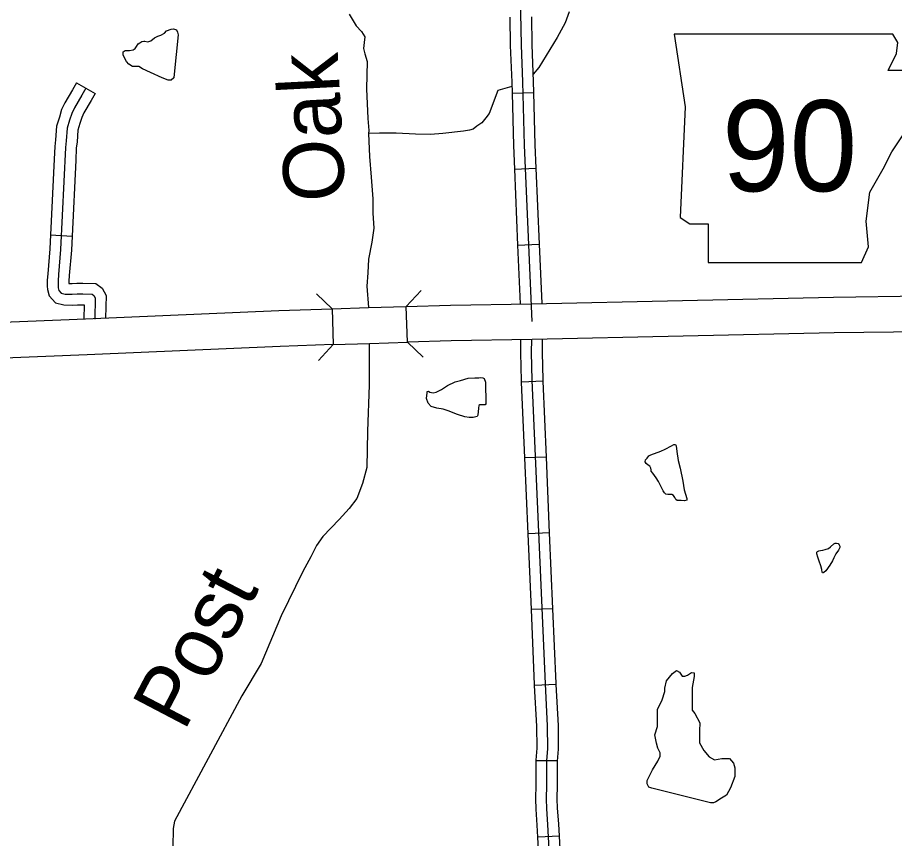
# Model space of a CAD drawing. Extents: x -5566 to 1759129, y -3726 to 731467.
# Drawn here: x -4559.17 to -4512.81, y 255.2 to 298.58 of the extents above; entities that cross this region are included whole.
import ezdxf

# ---------------------------------------------------------------- set-up
doc = ezdxf.new("R2010")
doc.units = 0
doc.layers.add('Default', color=7, linetype='Continuous')

msp = doc.modelspace()

# ---------------------------------------------------------------- linework, layer by layer
at = {"layer": 'Default'}
for p, q in [((-4556.053, 295.124), (-4555.065, 294.557)), ((-4533.027, 294.581), (-4531.889, 294.611)), ((-4532.902, 290.565), (-4531.763, 290.613)), ((-4557.423, 287.089), (-4556.285, 287.035)), ((-4532.731, 286.558), (-4531.593, 286.607)), ((-4531.384, 279.363), (-4532.522, 279.315)), ((-4531.212, 275.357), (-4532.35, 275.309)), ((-4531.04, 271.351), (-4532.178, 271.303)), ((-4530.868, 267.345), (-4532.006, 267.296)), ((-4530.696, 263.346), (-4531.833, 263.284)), ((-4530.619, 259.31), (-4531.758, 259.311)), ((-4530.527, 255.334), (-4531.665, 255.274))]:
    msp.add_line(p, q, dxfattribs=at)
for points in [[(-4533.588, 322.21), (-4533.452, 319.715), (-4533.448, 319.094), (-4533.525, 317.394), (-4533.512, 315.103), (-4533.614, 313.624), (-4533.583, 312.543), (-4533.528, 311.702), (-4533.389, 310.302), (-4533.282, 308.917), (-4533.035, 306.147), (-4532.777, 302.561), (-4532.669, 301.437), (-4532.594, 299.684), (-4532.55, 297.117), (-4532.473, 295.185), (-4532.386, 291.842), (-4531.989, 282.511)], [(-4541.635, 298.757), (-4541.264, 298.145), (-4540.994, 297.835), (-4540.802, 297.567), (-4540.837, 297.261), (-4540.871, 296.947), (-4540.815, 296.66), (-4540.694, 296.253), (-4540.717, 294.811), (-4540.645, 293.251), (-4540.599, 292.605), (-4540.624, 292.46), (-4540.558, 291.243), (-4540.48, 290.149), (-4540.389, 288.999), (-4540.379, 288.238), (-4540.336, 287.455), (-4540.445, 286.704), (-4540.617, 285.806), (-4540.652, 285.094), (-4540.696, 284.392), (-4540.622, 283.257)], [(-4533.145, 298.594), (-4533.12, 297.101), (-4533.043, 295.166), (-4533.027, 294.581)], [(-4532.006, 298.614), (-4531.981, 297.133), (-4531.904, 295.203), (-4531.889, 294.611)], [(-4530.002, 298.887), (-4530.216, 298.292)], [(-4530.216, 298.292), (-4530.643, 297.522), (-4531.618, 295.947), (-4531.92, 295.595)], [(-4551.934, 297.504), (-4551.752, 297.598), (-4551.591, 297.639), (-4551.396, 297.746), (-4551.301, 297.868), (-4551.039, 297.969), (-4550.925, 297.975), (-4550.77, 297.935), (-4550.703, 297.8), (-4550.676, 297.659), (-4550.884, 295.593), (-4550.911, 295.397), (-4551.053, 295.276), (-4551.207, 295.27), (-4551.517, 295.391), (-4552.143, 295.667)], [(-4552.143, 295.667), (-4552.553, 295.869), (-4552.755, 295.983), (-4552.943, 295.983), (-4553.098, 295.983), (-4553.286, 296.118), (-4553.401, 296.259), (-4553.582, 296.582), (-4553.582, 296.69), (-4553.582, 296.764), (-4553.481, 296.831), (-4553.253, 296.845), (-4553.058, 296.865), (-4552.95, 296.946), (-4552.876, 297.053), (-4552.795, 297.188), (-4552.708, 297.248), (-4552.593, 297.316), (-4552.499, 297.329), (-4552.432, 297.329), (-4552.277, 297.289), (-4552.129, 297.349), (-4551.934, 297.504)], [(-4556.053, 295.124), (-4556.259, 294.764), (-4556.658, 294.077), (-4556.836, 293.72), (-4556.956, 293.316), (-4557.111, 292.836), (-4557.154, 292.122), (-4557.197, 291.766), (-4557.23, 291.095)], [(-4555.559, 294.84), (-4555.766, 294.48), (-4556.156, 293.807), (-4556.304, 293.51), (-4556.412, 293.148), (-4556.547, 292.73), (-4556.587, 292.071), (-4556.629, 291.718), (-4556.89, 286.322), (-4556.997, 284.996), (-4557.024, 284.673), (-4557.024, 284.404), (-4557.018, 284.296), (-4556.984, 284.155), (-4556.856, 284.02), (-4556.648, 283.966), (-4556.27, 283.957), (-4556.015, 283.973), (-4555.719, 283.973), (-4555.221, 283.959), (-4555.127, 283.892), (-4555.06, 283.764), (-4555.088, 282.641)], [(-4533.034, 294.943), (-4533.774, 294.73), (-4534.239, 293.509), (-4534.413, 293.276), (-4534.622, 293.013), (-4534.897, 292.831), (-4535.082, 292.675), (-4535.27, 292.622), (-4535.595, 292.58), (-4536.684, 292.458), (-4537.338, 292.398), (-4538.128, 292.423), (-4539.15, 292.476), (-4540.038, 292.465), (-4540.624, 292.46)], [(-4555.065, 294.557), (-4555.273, 294.195), (-4555.655, 293.536), (-4555.773, 293.3), (-4555.868, 292.979), (-4555.982, 292.623), (-4556.019, 292.019), (-4556.061, 291.67), (-4556.092, 291.04)], [(-4533.027, 294.581), (-4532.955, 291.822), (-4532.902, 290.565)], [(-4531.889, 294.611), (-4531.817, 291.861), (-4531.763, 290.613)], [(-4557.23, 291.095), (-4557.423, 287.089)], [(-4556.092, 291.04), (-4556.285, 287.035)], [(-4532.902, 290.565), (-4532.731, 286.558)], [(-4531.763, 290.613), (-4531.593, 286.607)], [(-4557.423, 287.089), (-4557.458, 286.359), (-4557.565, 285.043), (-4557.594, 284.696), (-4557.594, 284.386), (-4557.583, 284.212), (-4557.503, 283.873), (-4557.157, 283.509), (-4556.727, 283.398), (-4556.259, 283.387), (-4555.997, 283.403), (-4555.958, 283.403)], [(-4556.285, 287.035), (-4556.321, 286.285), (-4556.43, 284.949), (-4556.455, 284.649), (-4556.455, 284.531), (-4556.281, 284.527), (-4556.033, 284.542), (-4555.958, 284.542)], [(-4532.731, 286.558), (-4532.599, 283.451)], [(-4531.593, 286.607), (-4531.46, 283.472)], [(-4555.958, 284.542), (-4555.711, 284.542), (-4555.032, 284.524), (-4554.686, 284.277), (-4554.487, 283.898), (-4554.517, 282.701)], [(-4538.619, 283.318), (-4537.839, 284.148)], [(-4543.37, 283.974), (-4542.538, 283.195)], [(-4538.619, 283.318), (-4536.289, 283.389), (-4532.007, 283.46), (-4516.043, 283.809), (-4511.332, 283.875), (-4508.74, 283.93), (-4506.718, 283.981), (-4502.156, 284.075), (-4501.411, 284.061), (-4500.558, 283.973), (-4499.927, 283.862), (-4499.457, 283.748), (-4499.029, 283.633), (-4498.597, 283.467), (-4498.134, 283.253), (-4497.502, 282.93), (-4496.811, 282.612), (-4493.211, 280.583)], [(-4555.958, 283.403), (-4555.727, 283.403), (-4555.639, 283.401), (-4555.658, 282.651)], [(-4542.538, 283.195), (-4540.616, 283.257), (-4538.619, 283.318)], [(-4493.211, 280.583), (-4494.144, 278.929), (-4497.676, 280.92), (-4498.331, 281.222), (-4498.964, 281.545), (-4499.336, 281.717), (-4499.618, 281.825), (-4499.929, 281.909), (-4500.315, 282.003), (-4500.819, 282.091), (-4501.527, 282.164), (-4502.155, 282.177), (-4506.674, 282.083), (-4508.696, 282.032), (-4511.299, 281.976), (-4516.009, 281.911), (-4531.971, 281.562), (-4536.245, 281.491), (-4538.561, 281.421), (-4538.619, 283.318)], [(-4560.391, 282.469), (-4555.573, 282.655), (-4545.348, 283.104), (-4542.538, 283.195), (-4542.477, 281.297)], [(-4542.477, 281.297), (-4545.276, 281.206), (-4555.494, 280.758), (-4560.318, 280.572), (-4560.391, 282.469)], [(-4540.587, 281.359), (-4540.588, 279.161), (-4540.674, 276.719), (-4540.703, 274.813), (-4540.938, 273.958), (-4541.235, 273.163), (-4541.634, 272.645), (-4542.174, 272.062), (-4543.022, 271.162), (-4543.369, 270.677), (-4543.659, 270.08), (-4544.093, 269.302), (-4545.238, 266.967), (-4546.285, 264.452), (-4547.316, 262.745)], [(-4542.477, 281.297), (-4540.557, 281.36), (-4538.561, 281.421)], [(-4537.732, 280.64), (-4538.561, 281.421)], [(-4532.522, 279.315), (-4532.525, 279.392), (-4532.561, 280.867), (-4532.56, 281.563)], [(-4531.268, 263.369), (-4531.956, 279.411), (-4531.991, 280.873), (-4531.99, 281.562)], [(-4531.384, 279.363), (-4531.387, 279.43), (-4531.422, 280.88), (-4531.421, 281.561)], [(-4542.477, 281.297), (-4543.256, 280.466)], [(-4536.04, 279.322), (-4535.744, 279.394), (-4535.349, 279.52), (-4534.987, 279.542), (-4534.779, 279.547), (-4534.686, 279.553), (-4534.565, 279.542), (-4534.499, 279.509), (-4534.439, 279.311), (-4534.417, 278.16), (-4534.455, 278.11), (-4534.614, 278.11), (-4534.729, 278.11), (-4534.779, 278.077), (-4534.806, 277.946), (-4534.839, 277.567), (-4534.866, 277.502), (-4535.091, 277.45), (-4535.289, 277.45), (-4535.524, 277.48), (-4535.919, 277.606)], [(-4535.919, 277.606), (-4536.396, 277.792), (-4536.664, 277.88), (-4537.01, 277.946), (-4537.3, 278.034), (-4537.465, 278.198), (-4537.542, 278.45), (-4537.52, 278.752), (-4537.509, 278.823), (-4537.448, 278.829), (-4537.366, 278.779), (-4537.202, 278.746), (-4537.037, 278.79), (-4536.758, 278.922), (-4536.44, 279.141), (-4536.04, 279.322)], [(-4532.35, 275.309), (-4532.522, 279.315)], [(-4531.212, 275.357), (-4531.384, 279.363)], [(-4525.281, 274.068), (-4525.413, 274.26), (-4525.583, 274.507), (-4525.671, 274.605), (-4525.682, 274.677), (-4525.692, 274.764), (-4525.747, 274.869), (-4525.835, 274.934), (-4525.934, 275.011), (-4525.983, 275.099), (-4525.972, 275.209), (-4525.89, 275.302), (-4525.802, 275.412), (-4525.698, 275.477), (-4525.161, 275.664), (-4524.936, 275.768), (-4524.596, 275.954), (-4524.47, 276.026), (-4524.382, 276.026), (-4524.355, 275.949), (-4524.317, 275.647), (-4524.24, 275.181), (-4524.147, 274.775)], [(-4531.04, 271.351), (-4531.212, 275.357)], [(-4532.178, 271.303), (-4532.35, 275.309)], [(-4524.147, 274.775), (-4523.993, 274.074), (-4523.933, 273.624), (-4523.785, 273.174), (-4523.785, 273.086), (-4523.911, 273.048), (-4524.086, 273.059), (-4524.207, 273.054), (-4524.306, 273.065), (-4524.371, 273.114), (-4524.426, 273.218), (-4524.492, 273.322), (-4524.585, 273.377), (-4524.684, 273.377), (-4524.799, 273.377), (-4524.892, 273.399), (-4524.97, 273.468), (-4525.041, 273.572), (-4525.133, 273.755), (-4525.281, 274.068)], [(-4532.006, 267.296), (-4532.178, 271.303)], [(-4530.868, 267.345), (-4531.04, 271.351)], [(-4516.482, 270.474), (-4516.296, 270.528), (-4516.192, 270.614), (-4516.02, 270.777), (-4515.948, 270.813), (-4515.876, 270.813), (-4515.794, 270.781), (-4515.745, 270.727), (-4515.695, 270.655), (-4515.695, 270.578), (-4515.767, 270.438), (-4515.921, 270.234), (-4516.011, 270.035), (-4516.084, 269.881)], [(-4516.084, 269.881), (-4516.233, 269.637), (-4516.45, 269.338), (-4516.554, 269.252), (-4516.581, 269.239), (-4516.617, 269.239), (-4516.636, 269.279), (-4516.654, 269.415), (-4516.712, 269.61), (-4516.803, 269.863), (-4516.866, 270.067), (-4516.911, 270.234), (-4516.911, 270.284), (-4516.911, 270.334), (-4516.884, 270.37), (-4516.816, 270.401), (-4516.717, 270.419), (-4516.595, 270.433), (-4516.482, 270.474)], [(-4531.833, 263.284), (-4531.836, 263.341), (-4532.006, 267.296)], [(-4530.696, 263.346), (-4530.699, 263.397), (-4530.868, 267.345)], [(-4525.399, 260.244), (-4525.473, 260.687), (-4525.344, 261.111), (-4525.344, 261.553), (-4525.344, 262.014), (-4525.086, 262.531), (-4524.957, 262.973), (-4524.957, 263.139), (-4524.865, 263.526), (-4524.551, 263.913), (-4524.33, 264.079), (-4524.183, 263.987), (-4524.035, 263.784), (-4523.888, 263.784), (-4523.759, 263.84), (-4523.538, 263.969), (-4523.409, 263.95), (-4523.409, 263.766), (-4523.501, 263.176), (-4523.501, 262.604), (-4523.501, 261.977), (-4523.372, 261.812), (-4523.096, 261.314), (-4523.114, 260.89), (-4523.114, 260.576), (-4523.114, 260.263)], [(-4531.758, 259.311), (-4531.758, 259.344), (-4531.706, 259.968), (-4531.716, 261.136), (-4531.833, 263.284)], [(-4528.475, 215.482), (-4528.84, 215.98), (-4529.093, 216.401), (-4529.177, 216.591), (-4529.247, 216.766), (-4529.324, 217.033), (-4529.402, 217.714), (-4529.795, 227.413), (-4530.238, 238.305), (-4530.419, 241.475), (-4530.54, 243.659), (-4530.797, 249.09), (-4530.873, 250.487), (-4530.955, 252.648), (-4531.13, 255.941), (-4531.19, 256.773), (-4531.205, 257.302), (-4531.19, 258.028), (-4531.188, 259.32), (-4531.136, 259.947), (-4531.147, 261.154), (-4531.268, 263.369)], [(-4530.619, 259.296), (-4530.566, 259.926), (-4530.577, 261.172), (-4530.696, 263.346)], [(-4547.316, 262.745), (-4550.87, 256.123), (-4550.948, 255.723), (-4550.965, 254.738), (-4550.847, 254.08), (-4550.792, 253.465), (-4550.775, 252.429), (-4550.968, 250.886), (-4551.324, 249.975), (-4551.712, 249.109), (-4552.106, 248.509), (-4552.594, 247.797), (-4553.116, 246.878), (-4553.808, 245.706), (-4554.358, 244.602), (-4555.202, 243.01), (-4556.225, 241.228), (-4556.624, 240.352), (-4556.725, 240.087), (-4556.811, 239.688), (-4556.819, 239.266), (-4556.596, 238.103), (-4556.475, 237.531), (-4556.296, 236.726)], [(-4523.114, 260.263), (-4522.893, 259.857), (-4522.616, 259.525), (-4522.322, 259.36), (-4521.934, 259.433), (-4521.529, 259.433), (-4521.326, 259.175), (-4521.253, 258.936), (-4521.253, 258.475), (-4521.474, 257.885), (-4521.695, 257.498), (-4521.953, 257.332), (-4522.248, 257.147), (-4522.377, 257.092), (-4522.543, 257.092), (-4525.639, 257.866), (-4525.805, 257.922), (-4525.878, 258.087), (-4525.878, 258.272), (-4525.602, 258.825), (-4525.325, 259.286), (-4525.196, 259.544), (-4525.196, 259.728), (-4525.325, 259.968), (-4525.399, 260.244)], [(-4531.665, 255.274), (-4531.698, 255.906), (-4531.759, 256.744), (-4531.775, 257.3), (-4531.76, 258.035), (-4531.758, 259.311)], [(-4530.527, 255.334), (-4530.561, 255.977), (-4530.621, 256.802), (-4530.636, 257.305), (-4530.621, 258.022), (-4530.619, 259.31)], [(-4531.473, 251.278), (-4531.524, 252.622), (-4531.665, 255.274)], [(-4530.335, 251.321), (-4530.386, 252.674), (-4530.527, 255.334)]]:
    msp.add_lwpolyline(points, dxfattribs=at)
msp.add_lwpolyline([(-4524.457, 297.708), (-4523.879, 293.854), (-4524.136, 288.008), (-4523.622, 287.687), (-4522.659, 287.687), (-4522.659, 285.631), (-4514.565, 285.631), (-4514.179, 286.466), (-4514.308, 287.815), (-4514.115, 289.357), (-4513.408, 290.577), (-4512.959, 291.477), (-4512.316, 292.44), (-4511.931, 293.468), (-4511.61, 294.303), (-4511.031, 295.01), (-4510.903, 295.459), (-4511.16, 295.781), (-4513.151, 295.781), (-4512.702, 296.68), (-4512.637, 297.258), (-4512.904, 297.702)], close=True, dxfattribs=at)

# ---------------------------------------------------------------- texts
for s, rotation, p in [('Oak', 92.9133, (-4541.841, 288.919)), ('Post', 62.3756, (-4550.361, 260.808))]:
    msp.add_text(s, height=3.2048, rotation=rotation, dxfattribs=at).set_placement(p)
msp.add_text('90', height=4.8071, dxfattribs=at).set_placement((-4521.931, 289.401))

doc.saveas('drawing.dxf')
